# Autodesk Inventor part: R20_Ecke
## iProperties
Created: 2008-05
Part Number: R20_Ecke
Material: 1.0037 St 37-2
Document SubType Name: Blech
Designer: Gawin
Density: 7.85 g/cm^3
Author: Gawin
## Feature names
1. Grobblech12
2. Biegung11
3. Grobblech13
4. Biegung12
5. Grobblech14
6. Biegung13
7. Ecke14
